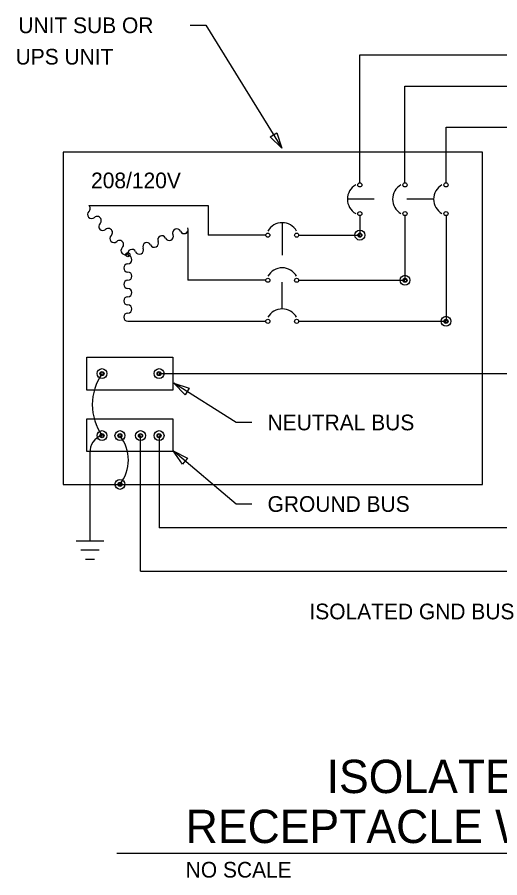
# Model space of a CAD drawing. Extents: x 10198.2 to 10245.1, y 10095.9 to 10133.7.
# Drawn here: x 10198.24 to 10218.76, y 10097.13 to 10133.72 of the extents above; entities that cross this region are included whole.
import ezdxf

# ---------------------------------------------------------------- set-up
doc = ezdxf.new("R2010")
doc.units = 0
for name, color, linetype in [('G-DETL-LINE', 7, 'Continuous'), ('G-DETL-TEXT', 7, 'Continuous'), ('G-DETL-TTXT', 7, 'Continuous')]:
    doc.layers.add(name, color=color, linetype=linetype)

msp = doc.modelspace()

# ---------------------------------------------------------------- linework, layer by layer
at = {"layer": 'G-DETL-LINE'}
for p, q in [((10212.806, 10132.117), (10225.37, 10132.117)), ((10212.806, 10126.681), (10212.806, 10132.117)), ((10212.806, 10132.117), (10225.37, 10132.117)), ((10212.806, 10126.681), (10212.806, 10132.117)), ((10214.725, 10130.796), (10223.625, 10130.796)), ((10214.725, 10126.681), (10214.725, 10130.796)), ((10214.725, 10130.796), (10223.625, 10130.796)), ((10214.725, 10126.681), (10214.725, 10130.796)), ((10216.47, 10129.049), (10221.706, 10129.049)), ((10216.47, 10126.681), (10216.47, 10129.049)), ((10216.47, 10129.049), (10221.706, 10129.049)), ((10216.47, 10126.681), (10216.47, 10129.049)), ((10218.021, 10127.989), (10200.189, 10127.989)), ((10200.189, 10127.989), (10200.189, 10113.856)), ((10218.021, 10127.989), (10200.189, 10127.989)), ((10200.189, 10127.989), (10200.189, 10113.856)), ((10218.021, 10113.856), (10218.021, 10127.989)), ((10218.021, 10113.856), (10218.021, 10127.989)), ((10213.415, 10125.983), (10212.277, 10125.983)), ((10213.415, 10125.983), (10212.277, 10125.983)), ((10215.941, 10125.983), (10214.803, 10125.983)), ((10215.941, 10125.983), (10214.803, 10125.983)), ((10201.283, 10125.721), (10206.35, 10125.721)), ((10201.283, 10125.721), (10206.35, 10125.721)), ((10206.35, 10125.721), (10206.35, 10124.456)), ((10206.35, 10125.721), (10206.35, 10124.456)), ((10212.806, 10125.285), (10212.806, 10124.456)), ((10212.806, 10125.285), (10212.806, 10124.456)), ((10214.725, 10125.285), (10214.725, 10122.537)), ((10214.725, 10125.285), (10214.725, 10122.537)), ((10216.47, 10125.285), (10216.47, 10120.792)), ((10216.47, 10125.285), (10216.47, 10120.792)), ((10209.506, 10124.985), (10209.506, 10123.6)), ((10209.506, 10124.985), (10209.506, 10123.6)), ((10205.494, 10124.621), (10205.494, 10122.537)), ((10205.494, 10124.621), (10205.494, 10122.537)), ((10208.808, 10124.456), (10206.35, 10124.456)), ((10208.808, 10124.456), (10206.35, 10124.456)), ((10210.203, 10124.456), (10212.806, 10124.456)), ((10210.203, 10124.456), (10212.806, 10124.456)), ((10208.808, 10122.537), (10205.494, 10122.537)), ((10208.808, 10122.537), (10205.494, 10122.537)), ((10209.506, 10121.321), (10209.506, 10122.453)), ((10209.506, 10121.321), (10209.506, 10122.453)), ((10210.203, 10122.537), (10214.725, 10122.537)), ((10210.203, 10122.537), (10214.725, 10122.537)), ((10202.941, 10120.792), (10208.808, 10120.792)), ((10202.941, 10120.792), (10208.808, 10120.792)), ((10210.203, 10120.792), (10216.47, 10120.792)), ((10210.203, 10120.792), (10216.47, 10120.792)), ((10201.196, 10117.869), (10201.196, 10119.265)), ((10201.196, 10117.869), (10201.196, 10119.265)), ((10201.196, 10119.265), (10204.86, 10119.265)), ((10204.86, 10119.265), (10204.86, 10117.869)), ((10204.262, 10118.568), (10221.921, 10118.568)), ((10204.86, 10117.869), (10201.196, 10117.869)), ((10201.196, 10115.252), (10201.196, 10116.648)), ((10201.196, 10116.648), (10204.86, 10116.648)), ((10201.196, 10115.252), (10201.196, 10116.648)), ((10204.86, 10116.648), (10204.86, 10115.252)), ((10203.479, 10110.168), (10203.479, 10115.93)), ((10204.269, 10115.93), (10204.269, 10112.01)), ((10204.86, 10115.252), (10201.196, 10115.252)), ((10204.86, 10115.252), (10201.196, 10115.252)), ((10201.328, 10115.203), (10201.328, 10111.461)), ((10201.328, 10115.203), (10201.328, 10111.461)), ((10200.189, 10113.856), (10218.021, 10113.856)), ((10200.189, 10113.856), (10218.021, 10113.856)), ((10224.391, 10112.01), (10204.269, 10112.01)), ((10200.742, 10111.461), (10201.914, 10111.461)), ((10200.938, 10111.071), (10201.719, 10111.071)), ((10201.133, 10110.68), (10201.524, 10110.68)), ((10203.479, 10110.168), (10227.774, 10110.168))]:
    msp.add_line(p, q, dxfattribs=at)
for centre, radius in [((10212.806, 10126.593), 0.0872), ((10212.806, 10126.593), 0.0872), ((10212.806, 10126.593), 0.0872), ((10212.806, 10126.593), 0.0872), ((10212.806, 10126.593), 0.0872), ((10212.806, 10126.593), 0.0872), ((10214.725, 10126.593), 0.0872), ((10214.725, 10126.593), 0.0872), ((10214.725, 10126.593), 0.0872), ((10214.725, 10126.593), 0.0872), ((10214.725, 10126.593), 0.0872), ((10214.725, 10126.593), 0.0872), ((10216.47, 10126.593), 0.0872), ((10216.47, 10126.593), 0.0872), ((10216.47, 10126.593), 0.0872), ((10216.47, 10126.593), 0.0872), ((10216.47, 10126.593), 0.0872), ((10216.47, 10126.593), 0.0872), ((10212.806, 10125.372), 0.0872), ((10212.806, 10125.372), 0.0872), ((10212.806, 10125.372), 0.0872), ((10212.806, 10125.372), 0.0872), ((10212.806, 10125.372), 0.0872), ((10212.806, 10125.372), 0.0872), ((10214.725, 10125.372), 0.0872), ((10214.725, 10125.372), 0.0872), ((10214.725, 10125.372), 0.0872), ((10214.725, 10125.372), 0.0872), ((10214.725, 10125.372), 0.0872), ((10214.725, 10125.372), 0.0872), ((10216.47, 10125.372), 0.0872), ((10216.47, 10125.372), 0.0872), ((10216.47, 10125.372), 0.0872), ((10216.47, 10125.372), 0.0872), ((10216.47, 10125.372), 0.0872), ((10216.47, 10125.372), 0.0872), ((10208.895, 10124.456), 0.0872), ((10208.895, 10124.456), 0.0872), ((10210.116, 10124.456), 0.0872), ((10210.116, 10124.456), 0.0872), ((10212.806, 10124.456), 0.211), ((10212.806, 10124.456), 0.211), ((10212.806, 10124.456), 0.0872), ((10212.806, 10124.456), 0.0872), ((10212.806, 10124.456), 0.0703), ((10212.806, 10124.456), 0.0703), ((10202.941, 10123.627), 0.0872), ((10202.941, 10123.627), 0.0872), ((10208.895, 10122.537), 0.0872), ((10208.895, 10122.537), 0.0872), ((10210.116, 10122.537), 0.0872), ((10210.116, 10122.537), 0.0872), ((10214.725, 10122.537), 0.211), ((10214.725, 10122.537), 0.211), ((10214.725, 10122.537), 0.0872), ((10214.725, 10122.537), 0.0872), ((10214.725, 10122.537), 0.0703), ((10214.725, 10122.537), 0.0703), ((10208.895, 10120.792), 0.0872), ((10208.895, 10120.792), 0.0872), ((10210.116, 10120.792), 0.0872), ((10210.116, 10120.792), 0.0872), ((10216.47, 10120.792), 0.211), ((10216.47, 10120.792), 0.211), ((10216.47, 10120.792), 0.0872), ((10216.47, 10120.792), 0.0872), ((10216.47, 10120.792), 0.0703), ((10216.47, 10120.792), 0.0703), ((10201.842, 10118.568), 0.211), ((10201.842, 10118.568), 0.0872), ((10201.842, 10118.568), 0.0872), ((10201.842, 10118.568), 0.0703), ((10204.269, 10118.568), 0.211), ((10204.269, 10118.568), 0.0872), ((10204.269, 10118.568), 0.0872), ((10204.269, 10118.568), 0.0703), ((10201.842, 10115.93), 0.211), ((10201.842, 10115.93), 0.0872), ((10201.842, 10115.93), 0.0872), ((10201.842, 10115.93), 0.0703), ((10202.604, 10115.93), 0.211), ((10202.604, 10115.93), 0.0872), ((10202.604, 10115.93), 0.0872), ((10202.604, 10115.93), 0.0703), ((10203.479, 10115.93), 0.211), ((10203.479, 10115.93), 0.0872), ((10203.479, 10115.93), 0.0872), ((10203.479, 10115.93), 0.0703), ((10204.269, 10115.93), 0.211), ((10204.269, 10115.93), 0.0872), ((10204.269, 10115.93), 0.0872), ((10204.269, 10115.93), 0.0703), ((10202.604, 10113.856), 0.211), ((10202.604, 10113.856), 0.0872), ((10202.604, 10113.856), 0.0872), ((10202.604, 10113.856), 0.0703)]:
    msp.add_circle(centre, radius, dxfattribs=at)
for centre, radius, start, end in [((10212.98, 10125.983), 0.703, 119.7449, 240.2551), ((10212.98, 10125.983), 0.703, 119.7449, 240.2551), ((10212.98, 10125.983), 0.703, 119.7449, 240.2551), ((10212.98, 10125.983), 0.703, 119.7449, 240.2551), ((10212.98, 10125.983), 0.703, 119.7449, 240.2551), ((10212.98, 10125.983), 0.703, 119.7449, 240.2551), ((10214.9, 10125.983), 0.703, 119.7449, 240.2551), ((10214.9, 10125.983), 0.703, 119.7449, 240.2551), ((10214.9, 10125.983), 0.703, 119.7449, 240.2551), ((10214.9, 10125.983), 0.703, 119.7449, 240.2551), ((10214.9, 10125.983), 0.703, 119.7449, 240.2551), ((10214.9, 10125.983), 0.703, 119.7449, 240.2551), ((10216.644, 10125.983), 0.703, 119.7449, 240.2551), ((10216.644, 10125.983), 0.703, 119.7449, 240.2551), ((10216.644, 10125.983), 0.703, 119.7449, 240.2551), ((10216.644, 10125.983), 0.703, 119.7449, 240.2551), ((10216.644, 10125.983), 0.703, 119.7449, 240.2551), ((10216.644, 10125.983), 0.703, 119.7449, 240.2551), ((10201.164, 10125.593), 0.174, 312.7516, 47.2484), ((10201.164, 10125.593), 0.174, 312.7516, 47.2484), ((10201.401, 10125.336), 0.174, 132.7516, 312.7516), ((10201.401, 10125.336), 0.174, 132.7516, 312.7516), ((10201.401, 10125.336), 0.174, 132.7516, 312.7516), ((10201.401, 10125.336), 0.174, 132.7516, 312.7516), ((10201.638, 10125.08), 0.174, 312.7516, 132.7516), ((10201.638, 10125.08), 0.174, 312.7516, 132.7516), ((10201.638, 10125.08), 0.174, 312.7516, 132.7516), ((10201.638, 10125.08), 0.174, 312.7516, 132.7516), ((10201.875, 10124.824), 0.174, 132.7516, 312.7516), ((10201.875, 10124.824), 0.174, 132.7516, 312.7516), ((10201.875, 10124.824), 0.174, 132.7516, 312.7516), ((10201.875, 10124.824), 0.174, 132.7516, 312.7516), ((10205.336, 10124.693), 0.174, 204.5593, 24.5593), ((10205.336, 10124.693), 0.174, 204.5593, 24.5593), ((10205.336, 10124.693), 0.174, 204.5593, 24.5593), ((10205.336, 10124.693), 0.174, 204.5593, 24.5593), ((10205.336, 10124.693), 0.174, 204.5593, 24.5593), ((10205.336, 10124.693), 0.174, 204.5593, 24.5593), ((10205.336, 10124.693), 0.174, 204.5593, 24.5593), ((10205.336, 10124.693), 0.174, 204.5593, 24.5593), ((10209.506, 10124.282), 0.703, 29.7449, 150.2551), ((10209.506, 10124.282), 0.703, 29.7449, 150.2551), ((10202.112, 10124.568), 0.174, 312.7516, 132.7516), ((10202.112, 10124.568), 0.174, 312.7516, 132.7516), ((10202.112, 10124.568), 0.174, 312.7516, 132.7516), ((10202.112, 10124.568), 0.174, 312.7516, 132.7516), ((10202.349, 10124.311), 0.174, 132.7516, 312.7516), ((10202.349, 10124.311), 0.174, 132.7516, 312.7516), ((10202.349, 10124.311), 0.174, 132.7516, 312.7516), ((10202.349, 10124.311), 0.174, 132.7516, 312.7516), ((10204.383, 10124.258), 0.174, 24.5593, 204.5593), ((10204.383, 10124.258), 0.174, 24.5593, 204.5593), ((10204.383, 10124.258), 0.174, 24.5593, 204.5593), ((10204.383, 10124.258), 0.174, 24.5593, 204.5593), ((10204.383, 10124.258), 0.174, 24.5593, 204.5593), ((10204.383, 10124.258), 0.174, 24.5593, 204.5593), ((10204.383, 10124.258), 0.174, 24.5593, 204.5593), ((10204.383, 10124.258), 0.174, 24.5593, 204.5593), ((10204.701, 10124.403), 0.174, 204.5593, 24.5593), ((10204.701, 10124.403), 0.174, 204.5593, 24.5593), ((10204.701, 10124.403), 0.174, 204.5593, 24.5593), ((10204.701, 10124.403), 0.174, 204.5593, 24.5593), ((10204.701, 10124.403), 0.174, 204.5593, 24.5593), ((10204.701, 10124.403), 0.174, 204.5593, 24.5593), ((10204.701, 10124.403), 0.174, 204.5593, 24.5593), ((10204.701, 10124.403), 0.174, 204.5593, 24.5593), ((10205.018, 10124.548), 0.174, 24.5593, 204.5593), ((10205.018, 10124.548), 0.174, 24.5593, 204.5593), ((10205.018, 10124.548), 0.174, 24.5593, 204.5593), ((10205.018, 10124.548), 0.174, 24.5593, 204.5593), ((10205.018, 10124.548), 0.174, 24.5593, 204.5593), ((10205.018, 10124.548), 0.174, 24.5593, 204.5593), ((10205.018, 10124.548), 0.174, 24.5593, 204.5593), ((10205.018, 10124.548), 0.174, 24.5593, 204.5593), ((10205.336, 10124.693), 0.174, 204.5593, 335.4407), ((10205.336, 10124.693), 0.174, 204.5593, 335.4407), ((10202.586, 10124.055), 0.174, 312.7516, 132.7516), ((10202.586, 10124.055), 0.174, 312.7516, 132.7516), ((10202.586, 10124.055), 0.174, 312.7516, 132.7516), ((10202.586, 10124.055), 0.174, 312.7516, 132.7516), ((10203.749, 10123.968), 0.174, 24.5593, 204.5593), ((10203.749, 10123.968), 0.174, 24.5593, 204.5593), ((10203.749, 10123.968), 0.174, 24.5593, 204.5593), ((10203.749, 10123.968), 0.174, 24.5593, 204.5593), ((10203.749, 10123.968), 0.174, 24.5593, 204.5593), ((10203.749, 10123.968), 0.174, 24.5593, 204.5593), ((10203.749, 10123.968), 0.174, 24.5593, 204.5593), ((10203.749, 10123.968), 0.174, 24.5593, 204.5593), ((10204.066, 10124.113), 0.174, 204.5593, 24.5593), ((10204.066, 10124.113), 0.174, 204.5593, 24.5593), ((10204.066, 10124.113), 0.174, 204.5593, 24.5593), ((10204.066, 10124.113), 0.174, 204.5593, 24.5593), ((10204.066, 10124.113), 0.174, 204.5593, 24.5593), ((10204.066, 10124.113), 0.174, 204.5593, 24.5593), ((10204.066, 10124.113), 0.174, 204.5593, 24.5593), ((10204.066, 10124.113), 0.174, 204.5593, 24.5593), ((10202.823, 10123.799), 0.174, 132.7516, 312.7516), ((10202.823, 10123.799), 0.174, 132.7516, 312.7516), ((10202.823, 10123.799), 0.174, 132.7516, 312.7516), ((10202.823, 10123.799), 0.174, 132.7516, 312.7516), ((10203.114, 10123.678), 0.174, 24.5593, 204.5593), ((10203.114, 10123.678), 0.174, 24.5593, 204.5593), ((10203.114, 10123.678), 0.174, 24.5593, 204.5593), ((10203.114, 10123.678), 0.174, 24.5593, 204.5593), ((10203.114, 10123.678), 0.174, 24.5593, 204.5593), ((10203.114, 10123.678), 0.174, 24.5593, 204.5593), ((10203.114, 10123.678), 0.174, 24.5593, 204.5593), ((10203.114, 10123.678), 0.174, 24.5593, 204.5593), ((10203.431, 10123.823), 0.174, 204.5593, 24.5593), ((10203.431, 10123.823), 0.174, 204.5593, 24.5593), ((10203.431, 10123.823), 0.174, 204.5593, 24.5593), ((10203.431, 10123.823), 0.174, 204.5593, 24.5593), ((10203.431, 10123.823), 0.174, 204.5593, 24.5593), ((10203.431, 10123.823), 0.174, 204.5593, 24.5593), ((10203.431, 10123.823), 0.174, 204.5593, 24.5593), ((10203.431, 10123.823), 0.174, 204.5593, 24.5593), ((10202.941, 10123.409), 0.174, 270, 90), ((10202.941, 10123.409), 0.174, 270, 90), ((10202.941, 10123.409), 0.174, 270, 90), ((10202.941, 10123.409), 0.174, 270, 90), ((10202.941, 10123.409), 0.174, 270, 90), ((10202.941, 10123.409), 0.174, 270, 90), ((10202.941, 10123.409), 0.174, 270, 90), ((10202.941, 10123.409), 0.174, 270, 90), ((10202.941, 10123.06), 0.174, 90, 270), ((10202.941, 10123.06), 0.174, 90, 270), ((10202.941, 10123.06), 0.174, 90, 270), ((10202.941, 10123.06), 0.174, 90, 270), ((10202.941, 10123.06), 0.174, 90, 270), ((10202.941, 10123.06), 0.174, 90, 270), ((10202.941, 10123.06), 0.174, 90, 270), ((10202.941, 10123.06), 0.174, 90, 270), ((10209.506, 10122.362), 0.703, 29.7449, 150.2551), ((10209.506, 10122.362), 0.703, 29.7449, 150.2551), ((10202.941, 10122.711), 0.174, 270, 90), ((10202.941, 10122.711), 0.174, 270, 90), ((10202.941, 10122.711), 0.174, 270, 90), ((10202.941, 10122.711), 0.174, 270, 90), ((10202.941, 10122.711), 0.174, 270, 90), ((10202.941, 10122.711), 0.174, 270, 90), ((10202.941, 10122.711), 0.174, 270, 90), ((10202.941, 10122.711), 0.174, 270, 90), ((10202.941, 10122.362), 0.174, 90, 270), ((10202.941, 10122.362), 0.174, 90, 270), ((10202.941, 10122.362), 0.174, 90, 270), ((10202.941, 10122.362), 0.174, 90, 270), ((10202.941, 10122.362), 0.174, 90, 270), ((10202.941, 10122.362), 0.174, 90, 270), ((10202.941, 10122.362), 0.174, 90, 270), ((10202.941, 10122.362), 0.174, 90, 270), ((10202.941, 10122.013), 0.174, 270, 90), ((10202.941, 10122.013), 0.174, 270, 90), ((10202.941, 10122.013), 0.174, 270, 90), ((10202.941, 10122.013), 0.174, 270, 90), ((10202.941, 10122.013), 0.174, 270, 90), ((10202.941, 10122.013), 0.174, 270, 90), ((10202.941, 10122.013), 0.174, 270, 90), ((10202.941, 10122.013), 0.174, 270, 90), ((10202.941, 10121.664), 0.174, 90, 270), ((10202.941, 10121.664), 0.174, 90, 270), ((10202.941, 10121.664), 0.174, 90, 270), ((10202.941, 10121.664), 0.174, 90, 270), ((10202.941, 10121.664), 0.174, 90, 270), ((10202.941, 10121.664), 0.174, 90, 270), ((10202.941, 10121.664), 0.174, 90, 270), ((10202.941, 10121.664), 0.174, 90, 270), ((10202.941, 10121.315), 0.174, 270, 90), ((10202.941, 10121.315), 0.174, 270, 90), ((10202.941, 10121.315), 0.174, 270, 90), ((10202.941, 10121.315), 0.174, 270, 90), ((10202.941, 10121.315), 0.174, 270, 90), ((10202.941, 10121.315), 0.174, 270, 90), ((10202.941, 10121.315), 0.174, 270, 90), ((10202.941, 10121.315), 0.174, 270, 90), ((10202.941, 10120.966), 0.174, 90, 270), ((10202.941, 10120.966), 0.174, 90, 270), ((10202.941, 10120.966), 0.174, 90, 270), ((10202.941, 10120.966), 0.174, 90, 270), ((10202.941, 10120.966), 0.174, 90, 270), ((10202.941, 10120.966), 0.174, 90, 270), ((10202.941, 10120.966), 0.174, 90, 270), ((10202.941, 10120.966), 0.174, 90, 270), ((10209.506, 10120.617), 0.703, 29.7449, 150.2551), ((10209.506, 10120.617), 0.703, 29.7449, 150.2551), ((10203.747, 10117.249), 2.317, 145.2928, 214.7072), ((10202.037, 10115.247), 0.71, 105.8909, 183.5716), ((10202.037, 10115.247), 0.71, 105.8909, 183.5716), ((10201.282, 10114.893), 1.68, 321.8921, 38.1079)]:
    msp.add_arc(centre, radius, start, end, dxfattribs=at)
at = {"layer": 'G-DETL-TEXT'}
for p, q in [((10205.585, 10133.38), (10206.252, 10133.38)), ((10206.252, 10133.38), (10209.492, 10128.156)), ((10207.547, 10116.489), (10204.898, 10118.166)), ((10208.214, 10116.489), (10207.547, 10116.489)), ((10207.547, 10113.021), (10204.865, 10115.277)), ((10208.214, 10113.021), (10207.547, 10113.021))]:
    msp.add_line(p, q, dxfattribs=at)
for points in [[(10209.282, 10128.81), (10209.492, 10128.156), (10208.999, 10128.635)], [(10205.372, 10117.669), (10204.898, 10118.166), (10205.551, 10117.951)], [(10205.268, 10114.721), (10204.865, 10115.277), (10205.482, 10114.976)]]:
    msp.add_lwpolyline(points, close=True, dxfattribs=at)
at = {"layer": 'G-DETL-TTXT'}
msp.add_line((10202.478, 10098.17), (10241.002, 10098.17), dxfattribs=at)

# ---------------------------------------------------------------- texts
at = {"layer": 'G-DETL-TEXT'}
for s, height, p in [('UNIT SUB OR', 0.66667, (10198.283, 10133.047)), ('UPS UNIT', 0.6667, (10198.167, 10131.711)), ('208/120V', 0.6667, (10201.377, 10126.449)), ('NEUTRAL BUS', 0.66667, (10208.881, 10116.156)), ('GROUND BUS', 0.6667, (10208.881, 10112.688)), ('ISOLATED GND BUS', 0.66667, (10210.661, 10108.118))]:
    msp.add_text(s, height=height, dxfattribs=at).set_placement(p)
at = {"layer": 'G-DETL-TTXT'}
for s, height, p in [('ISOLATED GROUND', 1.41667, (10211.393, 10100.728)), ('RECEPTACLE WIRING DIAGRAM', 1.41667, (10205.4, 10098.603)), ('NO SCALE', 0.6667, (10205.4, 10097.135))]:
    msp.add_text(s, height=height, dxfattribs=at).set_placement(p)

doc.saveas('drawing.dxf')
